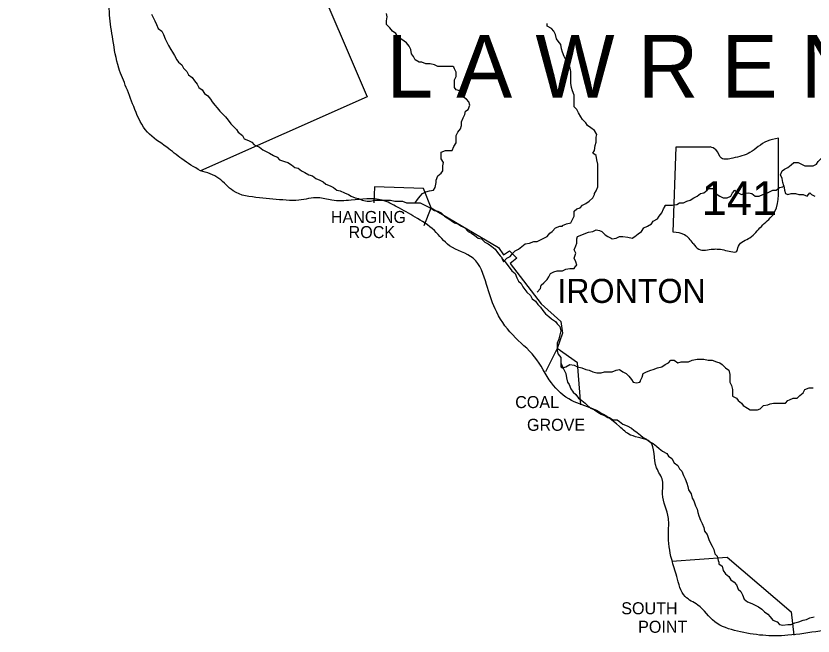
# Model space of a CAD drawing. Extents: x 0 to 34, y 0 to 22.
# Drawn here: x 6.387 to 7.678, y 14.864 to 15.869 of the extents above; entities that cross this region are included whole.
import ezdxf

# ---------------------------------------------------------------- set-up
doc = ezdxf.new("R2010")
doc.units = 0
doc.layers.add('Default', color=7, linetype='Continuous')
doc.layers.add('TR_Turning_Path1', color=7, linetype='Continuous')

msp = doc.modelspace()

# ---------------------------------------------------------------- linework, layer by layer
at = {"layer": 'Default'}
for points in [[(6.8735, 16.1142), (6.8626, 15.9546), (6.9553, 15.7379), (6.6853, 15.6179)], [(6.6062, 15.8715), (6.609, 15.866), (6.6117, 15.8606), (6.6144, 15.8551), (6.6171, 15.8483), (6.6226, 15.8442), (6.6253, 15.8387), (6.6281, 15.8319), (6.6308, 15.8265), (6.6335, 15.821), (6.6376, 15.8142), (6.6403, 15.8101), (6.6431, 15.8047), (6.6471, 15.7978), (6.6499, 15.7938), (6.6553, 15.7897), (6.658, 15.7842), (6.6635, 15.7788), (6.6662, 15.7733), (6.6717, 15.7692), (6.6758, 15.7638), (6.6799, 15.7583), (6.6826, 15.7529), (6.688, 15.7488), (6.6921, 15.7433), (6.6976, 15.7392), (6.7017, 15.7338), (6.7044, 15.7297), (6.7085, 15.7242), (6.7126, 15.7201), (6.7167, 15.7147), (6.7221, 15.7092), (6.7262, 15.7051), (6.7303, 15.6997), (6.7344, 15.6942), (6.7385, 15.6901), (6.7439, 15.6847), (6.7467, 15.6806), (6.7535, 15.6751), (6.7562, 15.6697), (6.763, 15.667), (6.7685, 15.6642), (6.7726, 15.6601), (6.7753, 15.6588)], [(7.0943, 15.7869), (7.0889, 15.7869), (7.0821, 15.7869), (7.0753, 15.7869), (7.0698, 15.7869), (7.0643, 15.7897), (7.0575, 15.791), (7.0507, 15.791), (7.0439, 15.7938), (7.0398, 15.7938), (7.033, 15.7978), (7.0303, 15.8033), (7.0275, 15.8074), (7.0262, 15.8142), (7.0234, 15.8197), (7.0194, 15.8251), (7.0153, 15.8278), (7.0098, 15.8319), (7.0044, 15.836), (7.0016, 15.8401), (6.9962, 15.8442), (6.9921, 15.8497), (6.9866, 15.8551), (6.9866, 15.8606), (6.988, 15.8674), (6.9866, 15.8728)], [(7.2825, 15.7869), (7.2811, 15.7938), (7.277, 15.7978), (7.2743, 15.8033), (7.2716, 15.8101), (7.2702, 15.8156), (7.2689, 15.8224), (7.2648, 15.8278), (7.262, 15.8319), (7.2607, 15.8387), (7.258, 15.8442), (7.2539, 15.8483), (7.247, 15.8524), (7.247, 15.8565)], [(7.1189, 15.7174), (7.1216, 15.7242), (7.1202, 15.7297), (7.1162, 15.7338), (7.1121, 15.7365), (7.108, 15.7406), (7.1053, 15.7474), (7.0998, 15.7488), (7.0971, 15.7529), (7.0971, 15.7583), (7.0971, 15.7651), (7.0998, 15.7706), (7.0998, 15.7774), (7.0971, 15.7828), (7.0957, 15.7856), (7.0943, 15.7869)], [(7.3275, 15.6356), (7.3261, 15.6424), (7.3207, 15.6465), (7.3234, 15.6506), (7.3248, 15.6588), (7.3261, 15.6642), (7.3261, 15.6724), (7.3275, 15.6765), (7.3234, 15.6833), (7.3179, 15.6874), (7.3125, 15.6915), (7.3098, 15.6956), (7.3043, 15.701), (7.3016, 15.7051), (7.2975, 15.7119), (7.2948, 15.7174), (7.2907, 15.7215), (7.2907, 15.7283), (7.2907, 15.7351), (7.2907, 15.7406), (7.2879, 15.7474), (7.2866, 15.7529), (7.2852, 15.7597), (7.2852, 15.7665), (7.2852, 15.7733), (7.2852, 15.7788), (7.2839, 15.7869), (7.2825, 15.7869)], [(7.078, 15.6192), (7.078, 15.6261), (7.0793, 15.6315), (7.0753, 15.637), (7.0753, 15.6424), (7.0753, 15.6479), (7.0821, 15.6506), (7.0889, 15.6506), (7.093, 15.6506), (7.0957, 15.6574), (7.0998, 15.6629), (7.0998, 15.6683), (7.0998, 15.6751), (7.1025, 15.6806), (7.1066, 15.686), (7.108, 15.6915), (7.108, 15.697), (7.1107, 15.7038), (7.1134, 15.7092), (7.1148, 15.7147), (7.1189, 15.7174), (7.1189, 15.7174)], [(7.6215, 15.6015), (7.6215, 15.6705)], [(6.7753, 15.6588), (6.7808, 15.656), (6.7862, 15.652), (6.7917, 15.6492), (6.7971, 15.6465), (6.8039, 15.6424), (6.8094, 15.6397), (6.8135, 15.6356), (6.8217, 15.6329), (6.8271, 15.6315), (6.8326, 15.6274), (6.838, 15.6233), (6.8435, 15.622), (6.8489, 15.6179), (6.8544, 15.6151), (6.8612, 15.6111), (6.8667, 15.6097), (6.8721, 15.6056), (6.8789, 15.6029), (6.8844, 15.6001), (6.8885, 15.5961), (6.8953, 15.5933), (6.9007, 15.5906), (6.9062, 15.5865), (6.9116, 15.5852), (6.9185, 15.5824), (6.9253, 15.5797), (6.9294, 15.577), (6.9362, 15.5742), (6.9416, 15.5729), (6.9471, 15.5702), (6.9553, 15.5688), (6.9607, 15.5688), (6.9675, 15.5702), (6.9744, 15.5702), (6.9798, 15.5702), (6.9866, 15.5702), (6.9934, 15.5702), (7.0003, 15.5688), (7.0071, 15.5688), (7.0125, 15.5688), (7.0194, 15.5661), (7.0262, 15.5661), (7.0275, 15.5661)], [(7.4512, 15.5186), (7.4558, 15.6567), (7.511, 15.6567)], [(7.3234, 15.5811), (7.3261, 15.5852), (7.3289, 15.592), (7.3289, 15.5988), (7.3289, 15.6042), (7.3289, 15.6097), (7.3289, 15.6179), (7.3289, 15.6233), (7.3289, 15.6288), (7.3275, 15.6356), (7.3275, 15.6356)], [(7.3234, 15.5811), (7.3261, 15.5852), (7.3289, 15.592), (7.3289, 15.5988), (7.3289, 15.6042), (7.3289, 15.6097), (7.3289, 15.6179), (7.3289, 15.6233), (7.3289, 15.6288), (7.3275, 15.6356), (7.3275, 15.6356)], [(7.6302, 15.5933), (7.6288, 15.5988), (7.6274, 15.6056), (7.6247, 15.6111), (7.6274, 15.6179), (7.6315, 15.6206), (7.637, 15.6233), (7.6424, 15.6274), (7.6465, 15.6315), (7.6533, 15.6315), (7.6588, 15.6288), (7.6643, 15.6261), (7.6711, 15.6261), (7.6779, 15.6261), (7.6833, 15.6288), (7.6861, 15.6329), (7.6915, 15.6383), (7.6956, 15.6424), (7.7024, 15.6465), (7.7024, 15.6465), (7.7038, 15.6479)], [(7.0275, 15.5661), (7.033, 15.5661), (7.0371, 15.5715), (7.0412, 15.577), (7.0453, 15.5811), (7.0507, 15.5838), (7.0562, 15.5852), (7.063, 15.5865), (7.0657, 15.5906), (7.0671, 15.5988), (7.0671, 15.6029), (7.0698, 15.6097), (7.0753, 15.6138), (7.078, 15.6179), (7.078, 15.6192)], [(7.048, 15.5293), (7.0589, 15.5579), (7.0466, 15.5892), (6.9675, 15.592), (6.9662, 15.5661)], [(7.4379, 15.562), (7.4434, 15.562), (7.4502, 15.562), (7.457, 15.5633), (7.4611, 15.5661), (7.4679, 15.5661), (7.4734, 15.5688), (7.4788, 15.5702), (7.4843, 15.5742), (7.4897, 15.577), (7.4952, 15.5811), (7.5006, 15.5824), (7.5061, 15.5865), (7.5088, 15.5892), (7.5156, 15.5892), (7.517, 15.5838), (7.5225, 15.5797), (7.5265, 15.577), (7.532, 15.5742), (7.532, 15.5742), (7.532, 15.5742)], [(7.532, 15.5742), (7.5388, 15.5742), (7.5443, 15.577), (7.547, 15.5824), (7.5511, 15.5865), (7.5565, 15.5824), (7.562, 15.5797), (7.5661, 15.5811), (7.5729, 15.5824), (7.5784, 15.5811), (7.5838, 15.577), (7.5906, 15.577), (7.5961, 15.5797), (7.6015, 15.5811), (7.607, 15.5838), (7.6124, 15.5865), (7.6179, 15.5865), (7.6234, 15.5906), (7.6288, 15.592), (7.6302, 15.5933)], [(7.6302, 15.5933), (7.6315, 15.5865), (7.6329, 15.5811), (7.637, 15.5797), (7.6424, 15.5811), (7.6493, 15.5811), (7.6547, 15.5797), (7.6615, 15.5797), (7.6683, 15.577), (7.6724, 15.5824), (7.6752, 15.5797), (7.6806, 15.577)], [(7.2716, 15.5293), (7.2784, 15.532), (7.2852, 15.5333), (7.2879, 15.5388), (7.2907, 15.5442), (7.2907, 15.5524), (7.2948, 15.5565), (7.3002, 15.5579), (7.3043, 15.562), (7.3098, 15.5647), (7.3152, 15.5688), (7.3207, 15.5742), (7.3234, 15.5797), (7.3234, 15.5811)], [(7.2716, 15.5293), (7.2784, 15.532), (7.2852, 15.5333), (7.2879, 15.5388), (7.2907, 15.5442), (7.2907, 15.5524), (7.2948, 15.5565), (7.3002, 15.5579), (7.3043, 15.562), (7.3098, 15.5647), (7.3152, 15.5688), (7.3207, 15.5742), (7.3234, 15.5797), (7.3234, 15.5811)], [(7.0275, 15.5661), (7.0344, 15.5661), (7.0412, 15.5661), (7.0466, 15.5633), (7.0521, 15.5606), (7.0575, 15.5579), (7.0643, 15.5538), (7.0698, 15.5524), (7.0753, 15.5497), (7.0807, 15.5442), (7.0848, 15.5415), (7.0916, 15.5374), (7.0971, 15.5333), (7.1025, 15.532), (7.108, 15.5279), (7.1134, 15.5252), (7.1189, 15.5197), (7.1243, 15.517), (7.1298, 15.5129), (7.1352, 15.5088), (7.1407, 15.5074), (7.1462, 15.502), (7.1516, 15.4993), (7.1571, 15.4952), (7.1625, 15.4911), (7.1666, 15.4856), (7.1707, 15.4802), (7.1734, 15.4774), (7.1734, 15.4774), (7.1734, 15.4761)], [(7.352, 15.5074), (7.3588, 15.5088), (7.3643, 15.5115), (7.3698, 15.5115), (7.3779, 15.5102), (7.3848, 15.5088), (7.3888, 15.5115), (7.3943, 15.5156), (7.3997, 15.5197), (7.4038, 15.5252), (7.4093, 15.5279), (7.4161, 15.532), (7.4188, 15.5361), (7.4257, 15.5402), (7.4284, 15.5442), (7.4325, 15.5497), (7.4352, 15.5565), (7.4379, 15.5606), (7.4379, 15.562)], [(7.0589, 15.5579), (7.168, 15.4938), (7.1761, 15.4815), (7.1857, 15.4883), (7.198, 15.4761), (7.1871, 15.4679), (7.2375, 15.4025), (7.2689, 15.3738), (7.2716, 15.3547), (7.2634, 15.3302)], [(7.1734, 15.4761), (7.1761, 15.4706), (7.1816, 15.4761), (7.1871, 15.4788), (7.1911, 15.4843), (7.1952, 15.4883), (7.2007, 15.4911), (7.2061, 15.4952), (7.2116, 15.4993), (7.2184, 15.5006), (7.2252, 15.5033), (7.2307, 15.5033), (7.2361, 15.5061), (7.2416, 15.5088), (7.247, 15.5115), (7.2511, 15.517), (7.2552, 15.5197), (7.2607, 15.5252), (7.2675, 15.5279), (7.2716, 15.5279), (7.2716, 15.5293)], [(7.1734, 15.4761), (7.1761, 15.4706), (7.1816, 15.4761), (7.1871, 15.4788), (7.1911, 15.4843), (7.1952, 15.4883), (7.2007, 15.4911), (7.2061, 15.4952), (7.2116, 15.4993), (7.2184, 15.5006), (7.2252, 15.5033), (7.2307, 15.5033), (7.2361, 15.5061), (7.2416, 15.5088), (7.247, 15.5115), (7.2511, 15.517), (7.2552, 15.5197), (7.2607, 15.5252), (7.2675, 15.5279), (7.2716, 15.5279), (7.2716, 15.5293)], [(7.2948, 15.4652), (7.2934, 15.4706), (7.2907, 15.4761), (7.2934, 15.4843), (7.2907, 15.4897), (7.2934, 15.4965), (7.2948, 15.5006), (7.2948, 15.5074), (7.2961, 15.5115), (7.3029, 15.5143), (7.3098, 15.517), (7.3139, 15.5183), (7.3207, 15.5197), (7.3261, 15.5224), (7.3316, 15.5211), (7.3357, 15.5197), (7.3411, 15.5143), (7.3452, 15.5115), (7.3507, 15.5088), (7.352, 15.5074), (7.352, 15.5074)], [(7.1734, 15.4761), (7.1789, 15.4706), (7.1816, 15.4665), (7.1871, 15.4597), (7.1898, 15.4556), (7.1952, 15.4515), (7.198, 15.4447), (7.2007, 15.4393), (7.2048, 15.4352), (7.2075, 15.4297), (7.2143, 15.4215), (7.2143, 15.4215)], [(7.2307, 15.4215), (7.2361, 15.427), (7.2375, 15.4324), (7.2416, 15.4365), (7.247, 15.442), (7.2498, 15.4461), (7.2525, 15.4515), (7.258, 15.4543), (7.2634, 15.4556), (7.2716, 15.4556), (7.277, 15.4584), (7.2839, 15.4597), (7.2907, 15.4597), (7.2934, 15.4638), (7.2948, 15.4652)], [(7.2143, 15.4215), (7.2198, 15.4161), (7.2225, 15.4106), (7.228, 15.4065), (7.232, 15.4011), (7.2361, 15.397), (7.2402, 15.3915), (7.2443, 15.3861), (7.2498, 15.382), (7.2539, 15.3779), (7.2607, 15.3738), (7.2634, 15.3697), (7.2675, 15.3656), (7.2689, 15.3588), (7.2675, 15.352), (7.2661, 15.3452), (7.2634, 15.3384), (7.2634, 15.3329), (7.2634, 15.3261), (7.2648, 15.3206), (7.2689, 15.3152), (7.2689, 15.307), (7.2689, 15.307)], [(7.3016, 15.2388), (7.2961, 15.307), (7.2634, 15.3302), (7.2443, 15.292)], [(7.2689, 15.307), (7.2716, 15.3002), (7.2743, 15.2947), (7.277, 15.2893), (7.2784, 15.2825), (7.2798, 15.2757), (7.2825, 15.2716), (7.2852, 15.2647), (7.2893, 15.2593), (7.2934, 15.2552), (7.2975, 15.2497), (7.3029, 15.2457), (7.3084, 15.2416), (7.3125, 15.2375), (7.3179, 15.2334), (7.3234, 15.2307), (7.3289, 15.2266), (7.3343, 15.2238), (7.3411, 15.2211), (7.3452, 15.2184), (7.3479, 15.2184)], [(7.2689, 15.307), (7.2689, 15.3002), (7.2716, 15.2988), (7.277, 15.3002), (7.2839, 15.3043), (7.2907, 15.3029), (7.2961, 15.3002), (7.3029, 15.2988), (7.3098, 15.2961), (7.3152, 15.2947), (7.3207, 15.292), (7.3275, 15.2907), (7.3343, 15.2907), (7.3398, 15.292), (7.3452, 15.292), (7.352, 15.292), (7.3588, 15.2947), (7.3643, 15.2961), (7.3698, 15.292), (7.3752, 15.2893), (7.3793, 15.2852), (7.3834, 15.2797), (7.3861, 15.2757), (7.3916, 15.2743), (7.397, 15.2757), (7.3984, 15.277), (7.3984, 15.2784)], [(7.3984, 15.2784), (7.4011, 15.2838), (7.4025, 15.2893), (7.4079, 15.292), (7.4147, 15.2947), (7.4188, 15.2961), (7.4257, 15.2988), (7.4325, 15.3002), (7.4379, 15.3043), (7.4434, 15.307), (7.4475, 15.3111), (7.4529, 15.3111), (7.4584, 15.307), (7.4638, 15.3084), (7.4706, 15.3084), (7.4761, 15.3084), (7.4816, 15.3111), (7.4897, 15.3125), (7.4952, 15.3125), (7.5006, 15.3125), (7.5075, 15.3111), (7.5143, 15.3111), (7.5211, 15.3084), (7.5265, 15.307), (7.5306, 15.3043), (7.5361, 15.2988), (7.5415, 15.2947), (7.5415, 15.2947), (7.5415, 15.2947)], [(7.5415, 15.2947), (7.5429, 15.2879), (7.5429, 15.2825), (7.5429, 15.2757), (7.5456, 15.2702), (7.547, 15.2634), (7.547, 15.2579), (7.547, 15.2525), (7.5538, 15.2497), (7.5565, 15.2457), (7.562, 15.2416), (7.5647, 15.2375), (7.5715, 15.2334), (7.5756, 15.2307), (7.5824, 15.2307), (7.5879, 15.2307), (7.592, 15.232), (7.592, 15.232)], [(7.6397, 15.247), (7.6452, 15.2497), (7.652, 15.2497), (7.6561, 15.2538), (7.6615, 15.2579), (7.6643, 15.2634), (7.6711, 15.2661), (7.6779, 15.2661)], [(7.592, 15.232), (7.5974, 15.2375), (7.6043, 15.2388), (7.6084, 15.2402), (7.6138, 15.2416), (7.6206, 15.2416), (7.6274, 15.2416), (7.6329, 15.2416), (7.637, 15.2457), (7.6397, 15.247)], [(7.3479, 15.2184), (7.3534, 15.2143), (7.3602, 15.2143), (7.3643, 15.2116), (7.3698, 15.2075), (7.3766, 15.2048), (7.3834, 15.2007), (7.3875, 15.1979), (7.3929, 15.1938), (7.3984, 15.1898), (7.4025, 15.1857), (7.4079, 15.1829), (7.4134, 15.1789), (7.4188, 15.1761), (7.4243, 15.172), (7.4284, 15.1679), (7.4338, 15.1639), (7.4407, 15.1598), (7.4434, 15.1557), (7.4488, 15.1516), (7.4529, 15.1448), (7.4584, 15.1407), (7.4611, 15.1352), (7.4652, 15.1311), (7.4679, 15.1243), (7.4706, 15.1189), (7.4734, 15.112), (7.4747, 15.1066), (7.4761, 15.1011), (7.4802, 15.0943), (7.4816, 15.0875), (7.4843, 15.0834), (7.487, 15.0752), (7.4897, 15.0698), (7.4911, 15.0643), (7.4925, 15.0589), (7.4952, 15.0521), (7.4979, 15.0466), (7.5006, 15.0398), (7.502, 15.0343), (7.5061, 15.0289), (7.5088, 15.0207), (7.5102, 15.0166), (7.5143, 15.0098), (7.517, 15.0043), (7.5184, 14.9975), (7.5225, 14.9934), (7.5238, 14.9866), (7.5252, 14.9839), (7.5252, 14.9812)], [(7.4488, 14.9852), (7.5388, 14.9921), (7.6424, 14.9034), (7.6465, 14.8653)], [(7.5252, 14.9812), (7.5306, 14.9771), (7.532, 14.9702), (7.5361, 14.9648), (7.5415, 14.9607), (7.5443, 14.9553), (7.5497, 14.9512), (7.5538, 14.9471), (7.5565, 14.9403), (7.5606, 14.9362), (7.5634, 14.9307), (7.5661, 14.9239), (7.5715, 14.9198), (7.5784, 14.9171), (7.5838, 14.9143), (7.5893, 14.9116), (7.5947, 14.9075), (7.5988, 14.9034), (7.6043, 14.8994), (7.6084, 14.8953), (7.6084, 14.8953), (7.6084, 14.8953)], [(7.6084, 14.8953), (7.6124, 14.8898), (7.6193, 14.8871), (7.6234, 14.883), (7.6288, 14.8816), (7.637, 14.883), (7.6424, 14.883), (7.6479, 14.8857), (7.6547, 14.8871), (7.6615, 14.8898), (7.667, 14.8912), (7.6724, 14.8939), (7.6793, 14.8953)]]:
    msp.add_lwpolyline(points, dxfattribs=at)
for points in [[(6.6853, 15.6179), (6.6553, 15.637), (6.6308, 15.656), (6.5994, 15.6806), (6.579, 15.7174), (6.5653, 15.7529), (6.5531, 15.7842), (6.5435, 15.8306), (6.5381, 15.8701), (6.5381, 15.9124), (6.5381, 15.9505), (6.5353, 16.0024), (6.5217, 16.0433), (6.5108, 16.0773), (6.4944, 16.1033), (6.4781, 16.1223), (6.4699, 16.1496), (6.4699, 16.1919), (6.4835, 16.2273), (6.4931, 16.2696), (6.4931, 16.3132), (6.4863, 16.3555), (6.4835, 16.3964), (6.4672, 16.4264), (6.4494, 16.4427), (6.4222, 16.4577), (6.4058, 16.4605), (6.3799, 16.4523), (6.3663, 16.4496), (6.3308, 16.44), (6.294, 16.4318), (6.2599, 16.4155), (6.2327, 16.3964), (6.2068, 16.38), (6.1754, 16.3623), (6.1495, 16.3473), (6.1304, 16.3364), (6.1072, 16.3282), (6.0718, 16.3296), (6.0377, 16.3364), (6.0036, 16.3391), (5.9654, 16.3459), (5.9395, 16.3282), (5.9163, 16.3105), (5.8973, 16.2696), (5.8795, 16.245), (5.8564, 16.2096), (5.8373, 16.1755), (5.8141, 16.166), (5.7746, 16.1496), (5.7418, 16.1332), (5.7009, 16.121), (5.6737, 16.106), (5.6368, 16.0896), (5.615, 16.0596), (5.6028, 16.0351), (5.5891, 15.9996), (5.5796, 15.9655), (5.5769, 15.9246), (5.5455, 15.896), (5.5114, 15.8701), (5.4637, 15.8469), (5.4132, 15.8469), (5.3723, 15.8387), (5.3273, 15.8387), (5.2837, 15.8442), (5.2428, 15.8633), (5.2169, 15.881), (5.1828, 15.8878), (5.1569, 15.8892), (5.1392, 15.8728), (5.1051, 15.8619), (5.0819, 15.8442)], [(8.5655, 15.6738), (8.545, 15.6479), (8.5382, 15.6233), (8.545, 15.5852), (8.5382, 15.5702), (8.5355, 15.5429), (8.5287, 15.517), (8.5287, 15.4965), (8.5287, 15.4679), (8.5232, 15.4461), (8.5137, 15.427), (8.5041, 15.4011), (8.5041, 15.3697), (8.5041, 15.3316), (8.5041, 15.2947), (8.4932, 15.2675), (8.4823, 15.232), (8.4741, 15.1938), (8.4714, 15.1679), (8.4646, 15.1407), (8.4496, 15.1039), (8.4332, 15.0671), (8.4182, 15.0521), (8.3869, 15.0343), (8.3555, 15.0302), (8.316, 15.0207), (8.2805, 15.0207), (8.2505, 15.0125), (8.2205, 15.0098), (8.196, 15.003), (8.1755, 15.003), (8.1537, 15.0125), (8.1333, 15.0234), (8.106, 15.0125), (8.0828, 15.003), (8.0624, 14.9934), (8.0365, 14.9866), (7.9983, 14.9784), (7.9642, 14.9675), (7.9342, 14.9607), (7.9042, 14.9498), (7.8729, 14.9362), (7.8401, 14.9239), (7.8088, 14.9143), (7.7733, 14.8953), (7.7406, 14.8816), (7.6888, 14.8721), (7.637, 14.8653), (7.5961, 14.8653), (7.5552, 14.8721), (7.5184, 14.8871), (7.4911, 14.9143), (7.4706, 14.928), (7.457, 14.9607), (7.4488, 14.988), (7.4434, 15.0302), (7.4434, 15.0548), (7.4338, 15.0943), (7.4338, 15.1161), (7.4243, 15.1366), (7.4134, 15.1789), (7.382, 15.1898), (7.3643, 15.2034), (7.3207, 15.232), (7.2866, 15.2457), (7.2539, 15.2743), (7.2266, 15.3166), (7.1911, 15.352), (7.1625, 15.3943), (7.1489, 15.4338), (7.1271, 15.4761), (7.0889, 15.4965), (7.0643, 15.5211), (7.033, 15.5429), (7.0044, 15.5592), (6.9798, 15.5702), (6.9294, 15.5702), (6.898, 15.5702), (6.8762, 15.5742), (6.8448, 15.5702), (6.8244, 15.5702), (6.7808, 15.5742), (6.7385, 15.5852), (6.7153, 15.6056), (6.6853, 15.6179)], [(7.6215, 15.6705), (7.6031, 15.6659), (7.5754, 15.6475), (7.5478, 15.6383), (7.5294, 15.6383), (7.5202, 15.6521), (7.511, 15.6567)], [(7.4834, 15.5002), (7.4926, 15.491), (7.5156, 15.491), (7.5248, 15.491), (7.5478, 15.4864), (7.5524, 15.4864), (7.557, 15.4956), (7.5754, 15.5094), (7.5939, 15.5278), (7.6123, 15.5462), (7.6215, 15.6015)], [(7.4834, 15.5002), (7.4696, 15.514), (7.4512, 15.5186)]]:
    msp.add_spline(points, degree=3, dxfattribs=at)

# ---------------------------------------------------------------- texts
for s, height, p in [('141', 0.05486, (7.4972, 15.5462)), ('HANGING', 0.0195, (6.8966, 15.5333)), ('ROCK', 0.0195, (6.9253, 15.5088)), ('IRONTON', 0.039, (7.2634, 15.4038)), ('COAL', 0.0195, (7.1952, 15.2334)), ('GROVE', 0.0195, (7.2143, 15.1966)), ('SOUTH', 0.0195, (7.367, 14.8994)), ('POINT', 0.0195, (7.3943, 14.8694))]:
    msp.add_text(s, height=height, dxfattribs=at).set_placement(p)
at = {"layer": 'TR_Turning_Path1'}
msp.add_text('L A W R E N C E', height=0.101489, dxfattribs=at).set_placement((6.9866, 15.7365))

doc.saveas('drawing.dxf')
